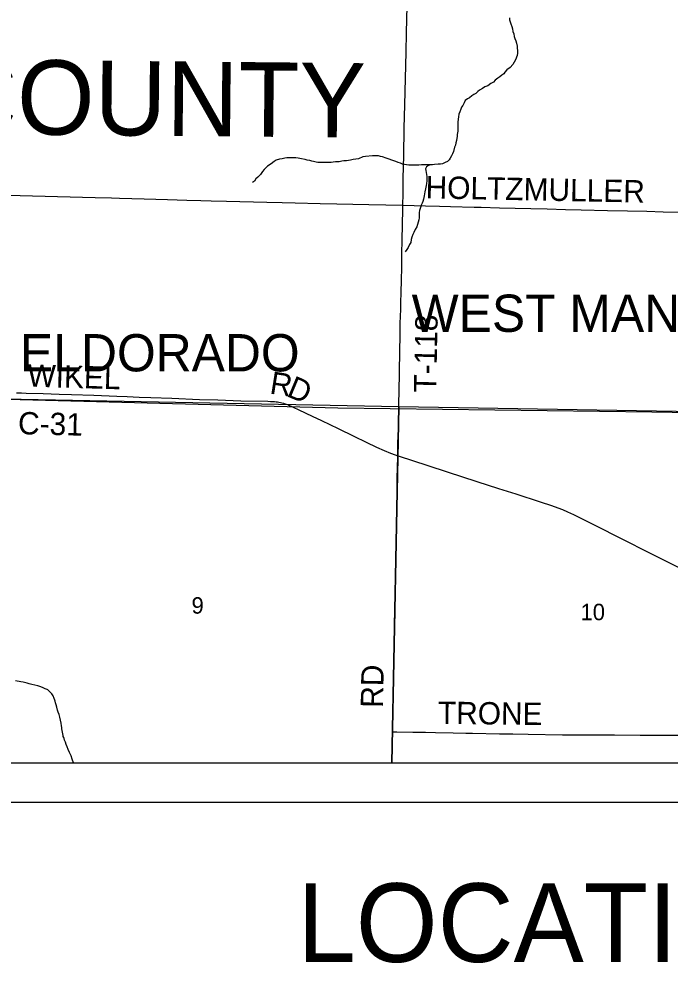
# Model space of a CAD drawing. Extents: x 0 to 1391, y -24 to 440.
# Drawn here: x 223.23 to 256.34, y 271.82 to 319.82 of the extents above; entities that cross this region are included whole.
import ezdxf

# ---------------------------------------------------------------- set-up
doc = ezdxf.new("R2010")
doc.units = 0
for name, color, linetype in [('GM_X_Adjacent_County_Text', 7, 'Continuous'), ('GM_X_Corporation', 7, 'Continuous'), ('GM_X_Corporation_Text', 7, 'Continuous'), ('GM_X_County_Road', 7, 'Continuous'), ('GM_X_County_Road_Text', 7, 'Continuous'), ('GM_X_Minor_River', 7, 'Continuous'), ('GM_X_Rail_Line', 7, 'Continuous'), ('GM_X_Section_Text', 7, 'Continuous'), ('GM_X_Township_Road', 7, 'Continuous'), ('GM_X_Township_Road_Text', 7, 'Continuous'), ('SH_Data', 7, 'Continuous'), ('SH_Text', 7, 'Continuous')]:
    doc.layers.add(name, color=color, linetype=linetype)

msp = doc.modelspace()

# ---------------------------------------------------------------- linework, layer by layer
at = {"layer": 'GM_X_Corporation'}
for points in [[(192, 321.564), (192, 282), (328, 282), (328, 319.315), (327.358, 319.321), (326.017, 319.331), (324.492, 319.344), (323.626, 319.346), (322.004, 319.36), (321.681, 319.364), (321.557, 319.363), (320.47, 319.355), (320.375, 319.355), (320.324, 319.361), (320.28, 319.374), (320.232, 319.401), (302.742, 319.575), (282.759, 319.815), (282.746, 319.815), (270.99, 319.899)], [(192, 321.564), (192, 282), (302.362, 282), (302.463, 287.791), (302.504, 290.987), (302.506, 291.392), (302.503, 291.694), (302.611, 309.266), (302.645, 314.81), (302.659, 314.843), (302.674, 314.915), (302.675, 315.033), (302.678, 315.834), (302.714, 317.94), (302.717, 318.152), (302.742, 319.575), (282.759, 319.815), (282.746, 319.815), (270.99, 319.899)]]:
    msp.add_lwpolyline(points, dxfattribs=at)
for points in [[(222.135, 282), (242.192, 282), (242.542, 300.093), (222.465, 300.489)], [(242.192, 282), (262.379, 282), (262.696, 299.764), (242.542, 300.093)]]:
    msp.add_lwpolyline(points, close=True, dxfattribs=at)
at = {"layer": 'GM_X_County_Road'}
msp.add_line((223.114, 300.816), (223.356, 300.808), dxfattribs=at)
for points in [[(223.356, 300.808), (223.599, 300.801), (224.468, 300.768), (225.276, 300.745), (225.897, 300.723), (227.04, 300.684), (228.207, 300.64), (228.728, 300.615), (229.349, 300.589), (229.945, 300.569), (231, 300.532), (232.416, 300.478), (233.347, 300.447), (234.514, 300.411), (235.883, 300.379), (236.015, 300.377), (236.129, 300.372), (236.222, 300.365), (236.305, 300.355), (236.381, 300.345), (236.449, 300.333), (236.532, 300.316), (236.6, 300.299), (236.678, 300.279), (236.758, 300.255), (236.827, 300.235), (236.897, 300.211), (236.988, 300.172), (237.078, 300.131), (237.172, 300.086), (237.464, 299.949), (238.135, 299.624), (238.606, 299.399), (239.458, 298.99), (240.249, 298.6), (240.888, 298.294), (241.407, 298.054), (241.794, 297.882), (242.127, 297.744), (242.36, 297.656), (242.488, 297.611), (242.56, 297.586), (243.247, 297.367), (244.028, 297.118), (244.997, 296.801), (246.51, 296.309), (247.62, 295.946), (248.497, 295.667), (249.739, 295.267), (250.305, 295.08), (250.621, 294.968), (250.864, 294.874), (251.114, 294.765), (251.417, 294.622), (251.906, 294.379), (252.717, 293.973), (253.682, 293.484), (255.494, 292.579), (257.869, 291.382)], [(242.209, 282), (242.211, 282.263), (242.226, 283.281), (242.231, 283.579), (242.254, 284.859), (242.262, 285.306), (242.272, 285.903), (242.283, 286.436), (242.29, 286.871), (242.309, 287.741), (242.332, 289.021), (242.374, 291.207), (242.396, 292.251), (242.422, 293.617), (242.436, 294.4), (242.453, 295.419), (242.466, 296.462), (242.482, 297.021), (242.487, 297.538), (242.488, 297.611)]]:
    msp.add_lwpolyline(points, dxfattribs=at)
at = {"layer": 'GM_X_Minor_River'}
for points in [[(248.167, 319.878), (248.179, 319.778), (248.24, 319.571), (248.282, 319.441), (248.316, 319.311), (248.349, 319.173), (248.384, 319.065), (248.41, 318.927), (248.444, 318.828), (248.493, 318.697), (248.52, 318.582), (248.554, 318.437), (248.566, 318.345), (248.576, 318.193), (248.58, 318.071), (248.568, 317.957), (248.47, 317.733), (248.405, 317.613), (248.333, 317.494), (248.206, 317.346), (248.042, 317.222), (247.94, 317.119), (247.877, 317.03), (247.776, 316.965), (247.681, 316.876), (247.573, 316.812), (247.448, 316.702), (247.353, 316.598), (247.221, 316.527), (247.073, 316.417), (246.912, 316.369), (246.795, 316.282), (246.648, 316.196), (246.554, 316.13), (246.452, 316.019), (246.351, 315.969), (246.258, 315.912), (246.141, 315.809), (246.033, 315.759), (245.923, 315.672), (245.866, 315.552), (245.793, 315.425), (245.737, 315.336), (245.696, 315.231), (245.646, 315.088), (245.604, 314.968), (245.584, 314.839), (245.565, 314.718), (245.553, 314.567), (245.538, 314.119), (245.517, 313.937), (245.507, 313.846), (245.488, 313.756), (245.477, 313.642), (245.443, 313.522), (245.424, 313.408), (245.375, 313.296), (245.322, 313.085), (245.272, 312.957), (245.223, 312.853), (245.159, 312.741), (245.103, 312.651), (245.024, 312.563), (244.908, 312.513), (244.769, 312.457), (244.662, 312.43), (244.54, 312.426), (244.357, 312.409), (244.25, 312.398), (244.151, 312.393), (243.908, 312.401), (243.809, 312.397), (243.695, 312.393), (243.558, 312.39), (243.413, 312.387), (243.291, 312.375), (243.2, 312.378), (243.048, 312.391), (242.942, 312.402), (242.828, 312.413), (242.738, 312.439), (242.632, 312.48), (242.505, 312.522), (242.399, 312.564), (242.189, 312.631), (242.053, 312.681), (241.896, 312.747), (241.707, 312.799), (241.617, 312.832), (241.511, 312.851), (241.291, 312.858), (241.199, 312.853), (240.848, 312.819), (240.711, 312.808), (240.495, 312.709), (240.227, 312.664), (240.089, 312.638)], [(240.089, 312.638), (239.883, 312.607), (239.753, 312.596), (239.654, 312.584), (239.516, 312.558), (239.326, 312.549), (239.204, 312.538), (239.112, 312.525), (238.952, 312.523), (238.83, 312.519), (238.724, 312.515), (238.571, 312.512), (238.427, 312.525), (238.336, 312.535), (238.215, 312.562), (238.117, 312.58), (238.019, 312.614), (237.891, 312.633), (237.778, 312.667), (237.596, 312.703), (237.43, 312.732), (237.301, 312.758), (237.187, 312.762), (237.035, 312.759), (236.845, 312.75), (236.745, 312.738), (236.607, 312.705), (236.485, 312.686), (236.308, 312.631), (236.2, 312.566), (236.052, 312.457), (235.865, 312.326), (235.707, 312.156), (235.613, 312.068), (235.517, 311.912), (235.375, 311.772), (235.281, 311.692), (235.209, 311.572), (235.108, 311.5)], [(244.151, 312.393), (244.059, 312.358), (243.958, 312.301), (243.909, 312.204), (243.914, 312.105), (243.953, 311.906), (243.965, 311.799), (243.968, 311.685), (243.973, 311.594), (243.946, 311.45), (243.935, 311.352), (243.899, 311.186), (243.871, 311.035), (243.852, 310.921), (243.834, 310.823), (243.798, 310.65), (243.764, 310.544), (243.738, 310.446), (243.689, 310.349), (243.655, 310.236), (243.597, 310.071), (243.586, 309.98), (243.577, 309.7), (243.567, 309.609), (243.532, 309.488), (243.498, 309.36), (243.456, 309.248), (243.383, 309.113), (243.31, 308.964), (243.253, 308.859), (243.211, 308.724), (243.177, 308.603), (243.149, 308.445), (243.092, 308.355), (243.019, 308.206), (242.955, 308.101), (242.875, 307.975)], [(226.001, 282), (225.937, 282.178), (225.88, 282.354), (225.807, 282.53), (225.742, 282.683), (225.683, 282.82), (225.632, 282.935), (225.597, 283.057), (225.553, 283.157), (225.524, 283.233), (225.51, 283.286), (225.488, 283.347), (225.481, 283.393), (225.433, 283.644), (225.419, 283.728), (225.405, 283.789), (225.391, 283.873), (225.378, 284.017), (225.343, 284.177), (225.308, 284.322), (225.272, 284.46), (225.229, 284.582), (225.2, 284.673), (225.158, 284.826), (225.13, 284.948), (225.115, 285.001), (225.093, 285.055), (225.08, 285.131), (225.058, 285.192), (225.029, 285.276), (224.971, 285.406), (224.897, 285.513), (224.83, 285.583), (224.793, 285.629), (224.704, 285.706), (224.659, 285.722), (224.614, 285.746), (224.561, 285.769), (224.471, 285.809), (224.336, 285.857), (224.185, 285.912), (224.035, 285.952), (223.884, 285.985), (223.756, 286.018), (223.651, 286.05), (223.44, 286.099), (223.319, 286.116), (223.048, 286.166)]]:
    msp.add_lwpolyline(points, dxfattribs=at)
at = {"layer": 'GM_X_Rail_Line'}
msp.add_lwpolyline([(192, 303.419), (194.214, 302.463), (195.22, 302.051), (196.525, 301.61), (197.947, 301.277), (199.299, 301.051), (199.919, 301.02), (201.585, 300.902), (205.579, 300.75), (223.288, 300.473), (239.448, 300.051), (255.408, 299.837), (261.625, 299.739)], dxfattribs=at)
at = {"layer": 'GM_X_Township_Road'}
for points in [[(242.488, 297.611), (242.5, 298.282), (242.52, 298.854), (242.539, 300.196), (242.558, 300.954), (242.574, 301.762), (242.596, 303.029), (242.61, 303.626), (242.621, 304.359), (242.629, 304.682), (242.642, 305.067), (242.648, 305.452), (242.656, 305.863), (242.68, 306.596), (242.69, 307.13), (242.698, 307.876), (242.716, 308.584), (242.749, 310.137), (242.753, 310.345), (242.764, 310.933), (242.773, 311.728), (242.797, 312.859), (242.824, 314.263), (242.851, 315.444), (242.918, 318.131), (242.941, 319.108), (242.964, 320.489)], [(222.643, 310.851), (223.286, 310.841), (225.2, 310.798), (227.113, 310.739), (227.945, 310.715), (228.343, 310.707), (229.597, 310.664), (230.79, 310.633), (231.759, 310.607), (232.479, 310.589), (233.001, 310.576), (233.784, 310.56), (235.834, 310.502), (236.616, 310.481), (237.275, 310.462), (238.554, 310.434), (239.391, 310.417), (241.027, 310.385), (242.753, 310.345), (243.909, 310.315), (244.605, 310.297), (245.176, 310.286), (246.382, 310.255), (246.729, 310.243), (247.661, 310.217), (249.251, 310.178), (250.084, 310.159), (251.025, 310.136), (251.811, 310.116), (253.153, 310.086), (254.171, 310.065), (255.153, 310.042), (255.985, 310.016), (256.755, 309.998)], [(242.231, 283.579), (242.445, 283.576), (243.257, 283.562), (243.894, 283.554), (244.416, 283.542), (245.31, 283.523), (245.956, 283.515), (246.291, 283.511), (247.658, 283.48), (248.341, 283.468), (249.124, 283.451), (250.863, 283.431), (252.193, 283.419), (253.51, 283.415), (254.815, 283.409), (255.809, 283.407), (256.9, 283.402)]]:
    msp.add_lwpolyline(points, dxfattribs=at)
at = {"layer": 'SH_Data'}
for p, q in [((192, 282), (328, 282)), ((190, 280), (330, 280)), ((190, 280), (330, 280))]:
    msp.add_line(p, q, dxfattribs=at)

# ---------------------------------------------------------------- texts
at = {"layer": 'GM_X_Adjacent_County_Text'}
msp.add_text('PREBLE COUNTY', height=3.78788, rotation=359.4491, dxfattribs=at).set_placement((198.066, 314.189))
at = {"layer": 'GM_X_Corporation_Text'}
for s, height, p in [('WEST MANCHESTER', 1.89394, (243.198, 303.909)), ('ELDORADO', 1.8939, (223.289, 301.901))]:
    msp.add_text(s, height=height, rotation=0, dxfattribs=at).set_placement(p)
at = {"layer": 'GM_X_County_Road_Text'}
for s, height, rotation, p in [('WIKEL', 1.1364, 358.2903, (223.652, 301.128)), ('R', 1.136, 351.0375, (235.943, 300.78)), ('D', 1.136, 337.1176, (236.795, 300.655)), ('C-31', 1.1364, 358.6274, (223.175, 298.708)), ('RD', 1.1364, 89.0123, (241.742, 284.789))]:
    msp.add_text(s, height=height, rotation=rotation, dxfattribs=at).set_placement(p)
at = {"layer": 'GM_X_Section_Text'}
for s, height, p in [('9', 0.837, (232.006, 289.583)), ('10', 0.8371, (251.781, 289.25))]:
    msp.add_text(s, height=height, rotation=0, dxfattribs=at).set_placement(p)
at = {"layer": 'GM_X_Township_Road_Text'}
for s, height, rotation, p in [('HOLTZMULLER', 1.13636, 358.8839, (243.898, 310.696)), ('T-118', 1.1364, 88.8768, (244.444, 300.81)), ('TRONE', 1.1364, 359.3813, (244.527, 283.979))]:
    msp.add_text(s, height=height, rotation=rotation, dxfattribs=at).set_placement(p)
at = {"layer": 'SH_Text'}
msp.add_text('LOCATION MAP', height=4, dxfattribs=at).set_placement((237.383, 271.875))

doc.saveas('drawing.dxf')
